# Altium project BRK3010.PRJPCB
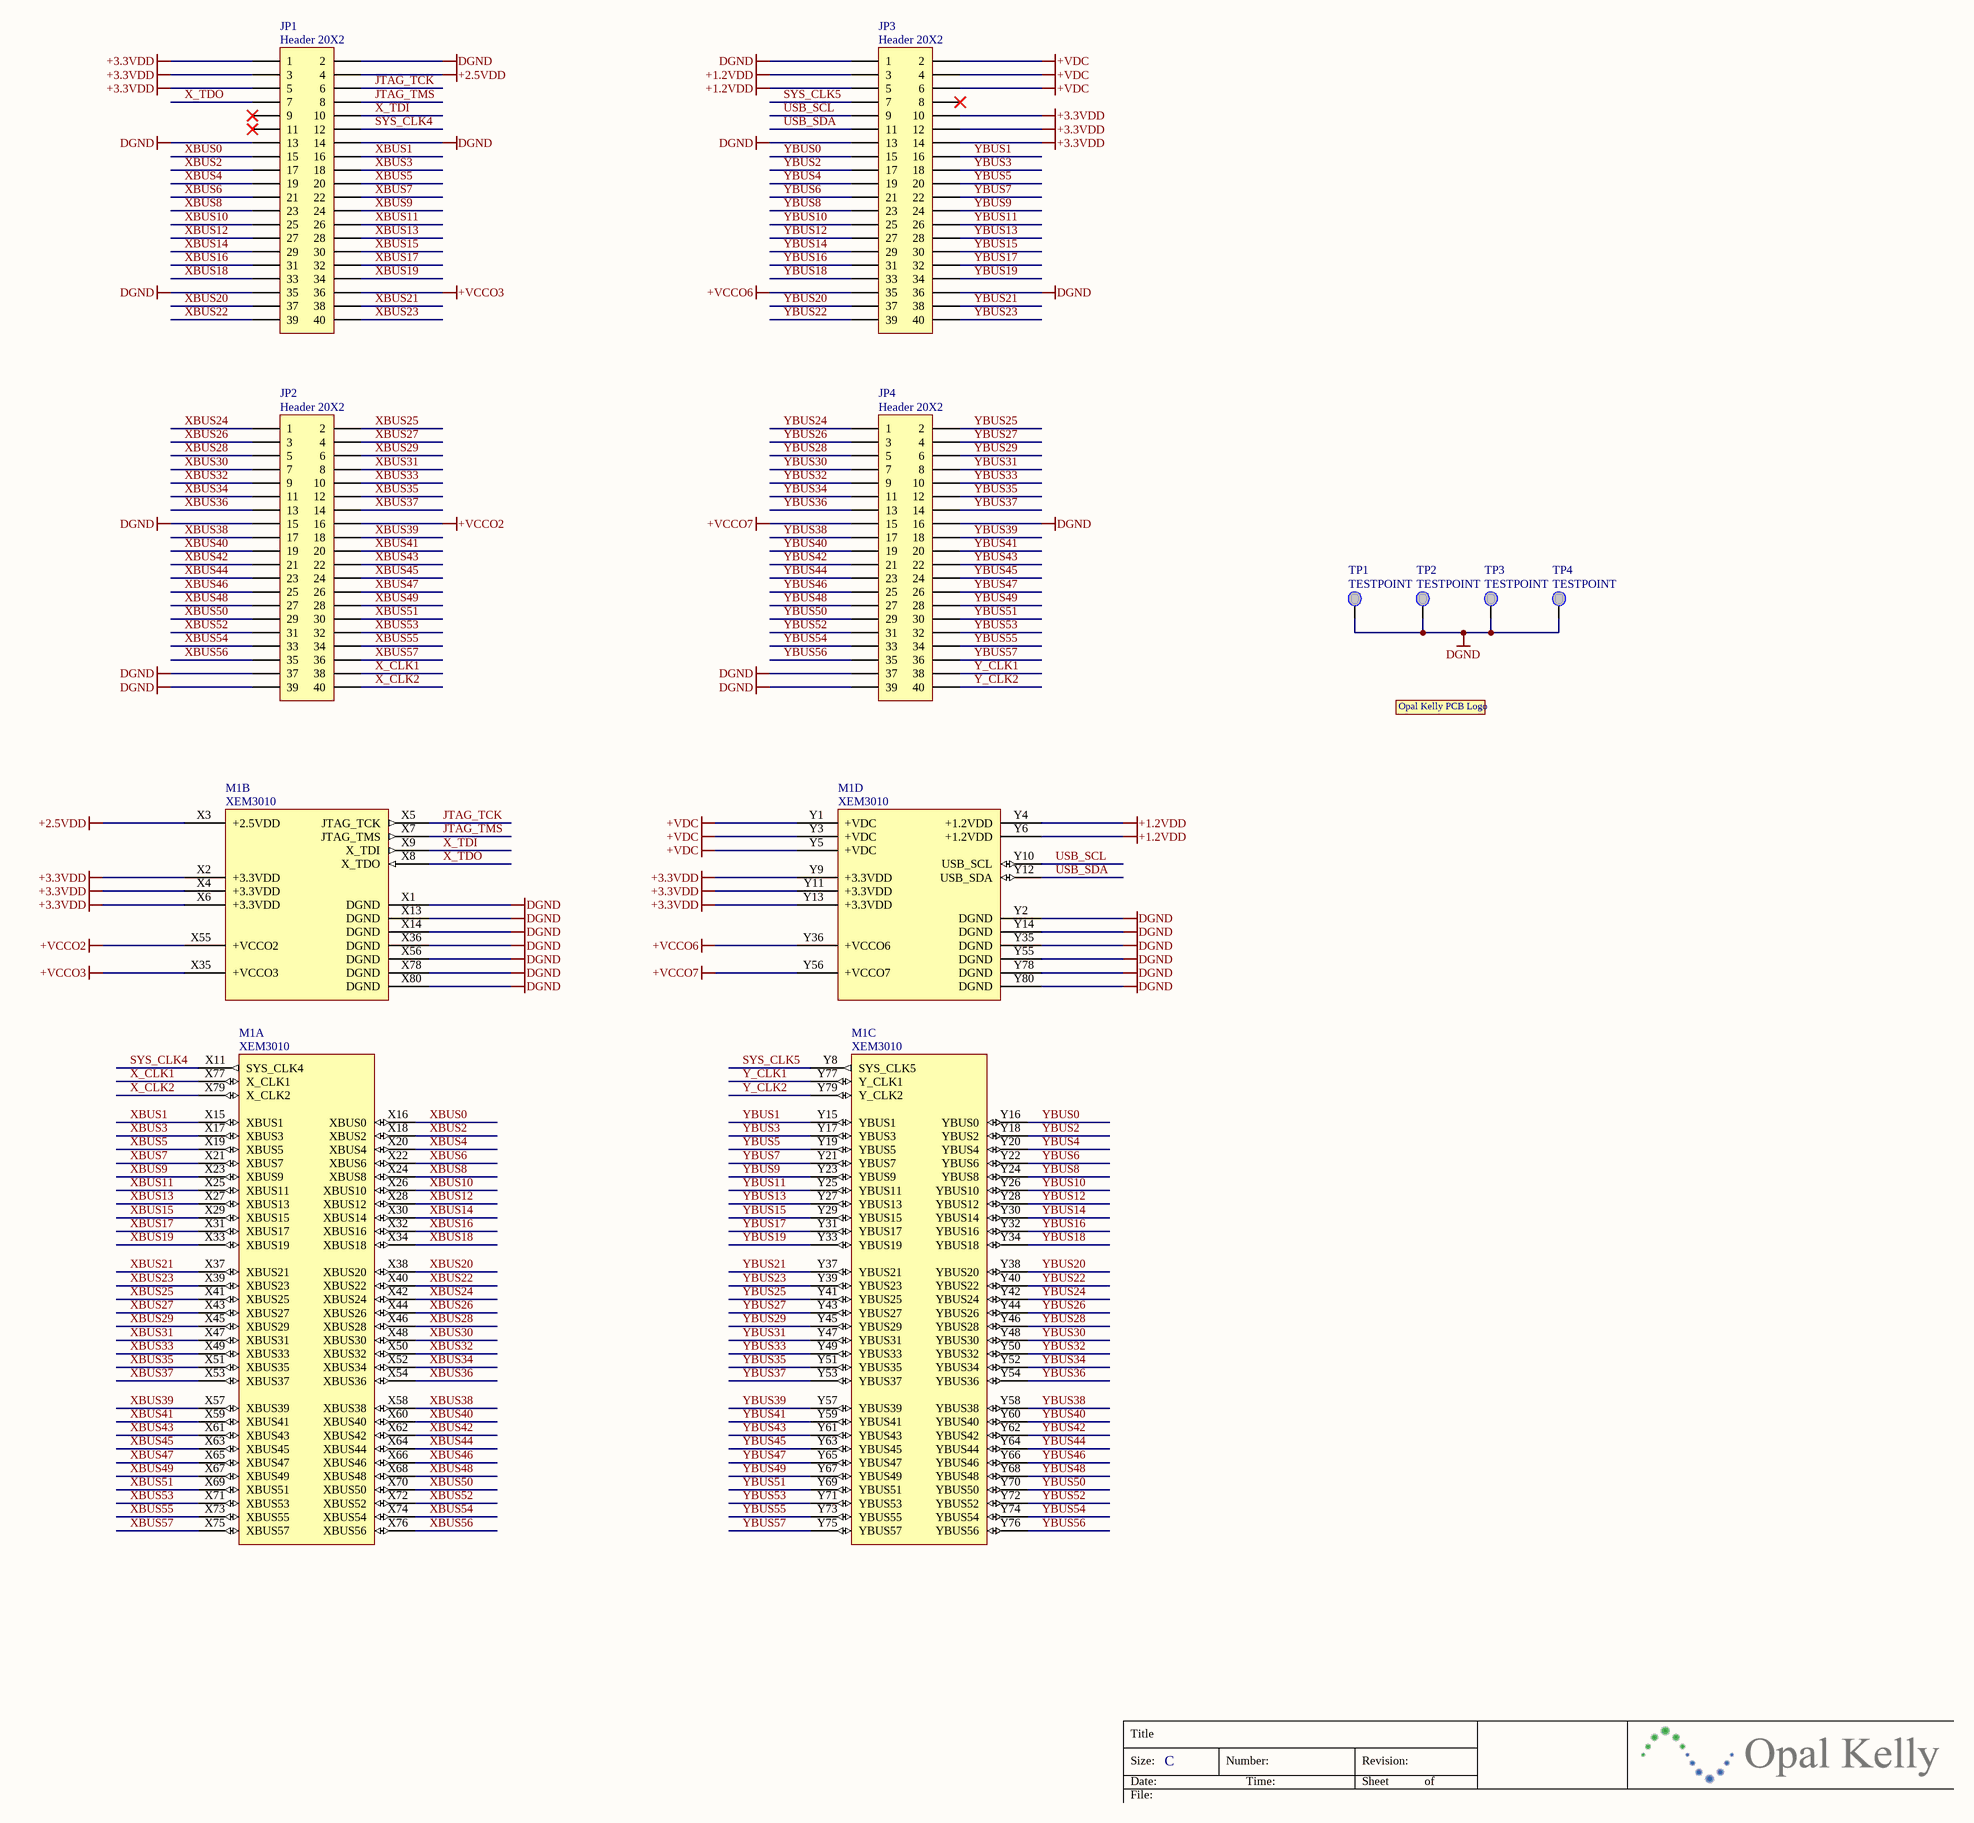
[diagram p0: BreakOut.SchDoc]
1 sheet, 10 parts. Net scope: global (net labels, ports and power ports of the same name join across sheets).
Board file: BreakOut.PcbDoc

## Sheet BreakOut.SchDoc: BRK3010
size C; Author: Garrick Kremesec; Organization: Opal Kelly; Address1: 13500 SW 72nd Ave, STE 120; Address2: Portland, OR 97223; Address3: http://www.opalkelly.com; DocumentNumber: 1; Revision: 1.0; SheetNumber: 1; SheetTotal: 1

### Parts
JP1  Header 20X2  [HDR2X20]
JP2  Header 20X2  [HDR2X20]
JP3  Header 20X2  [HDR2X20]
JP4  Header 20X2  [HDR2X20]
M1  XEM3010  [XEM3010MODULE]  (parts A,B,C,D of 4)
TP1  TESTPOINT  [TP_MED]
TP2  TESTPOINT  [TP_MED]
TP3  TESTPOINT  [TP_MED]
TP4  TESTPOINT  [TP_MED]
  OKLOGO  [oklogosmall]  (value not drawn)

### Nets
+1.2VDD: JP3.3 JP3.5 M1.Y4(+1.2VDD) M1.Y6(+1.2VDD)
+2.5VDD: JP1.4 M1.X3(+2.5VDD)
+3.3VDD: JP1.1 JP1.3 JP1.5 JP3.10 JP3.12 JP3.14 M1.X2(+3.3VDD) M1.X4(+3.3VDD) M1.X6(+3.3VDD) M1.Y9(+3.3VDD) M1.Y11(+3.3VDD) M1.Y13(+3.3VDD)
+VCCO2: JP2.16 M1.X55(+VCCO2)
+VCCO3: JP1.36 M1.X35(+VCCO3)
+VCCO6: JP3.35 M1.Y36(+VCCO6)
+VCCO7: JP4.15 M1.Y56(+VCCO7)
+VDC: JP3.2 JP3.4 JP3.6 M1.Y1(+VDC) M1.Y3(+VDC) M1.Y5(+VDC)
DGND: JP1.2 JP1.13 JP1.14 JP1.35 JP2.15 JP2.37 JP2.39 JP3.1 JP3.13 JP3.36 JP4.16 JP4.37 JP4.39 M1.X1(DGND) M1.X13(DGND) M1.X14(DGND) M1.X36(DGND) M1.X56(DGND) M1.X78(DGND) M1.X80(DGND) M1.Y2(DGND) M1.Y14(DGND) M1.Y35(DGND) M1.Y55(DGND) M1.Y78(DGND) M1.Y80(DGND) TP1.1(PIN) TP2.1(PIN) TP3.1(PIN) TP4.1(PIN)
JTAG_TCK: JP1.6 M1.X5(JTAG_TCK)
JTAG_TMS: JP1.8 M1.X7(JTAG_TMS)
SYS_CLK4: JP1.12 M1.X11(SYS_CLK4)
SYS_CLK5: JP3.7 M1.Y8(SYS_CLK5)
USB_SCL: JP3.9 M1.Y10(USB_SCL)
USB_SDA: JP3.11 M1.Y12(USB_SDA)
X_CLK1: JP2.38 M1.X77(X_CLK1)
X_CLK2: JP2.40 M1.X79(X_CLK2)
X_TDI: JP1.10 M1.X9(X_TDI)
X_TDO: JP1.7 M1.X8(X_TDO)
XBUS0: JP1.15 M1.X16(XBUS0)
XBUS1: JP1.16 M1.X15(XBUS1)
XBUS2: JP1.17 M1.X18(XBUS2)
XBUS3: JP1.18 M1.X17(XBUS3)
XBUS4: JP1.19 M1.X20(XBUS4)
XBUS5: JP1.20 M1.X19(XBUS5)
XBUS6: JP1.21 M1.X22(XBUS6)
XBUS7: JP1.22 M1.X21(XBUS7)
XBUS8: JP1.23 M1.X24(XBUS8)
XBUS9: JP1.24 M1.X23(XBUS9)
XBUS10: JP1.25 M1.X26(XBUS10)
XBUS11: JP1.26 M1.X25(XBUS11)
XBUS12: JP1.27 M1.X28(XBUS12)
XBUS13: JP1.28 M1.X27(XBUS13)
XBUS14: JP1.29 M1.X30(XBUS14)
XBUS15: JP1.30 M1.X29(XBUS15)
XBUS16: JP1.31 M1.X32(XBUS16)
XBUS17: JP1.32 M1.X31(XBUS17)
XBUS18: JP1.33 M1.X34(XBUS18)
XBUS19: JP1.34 M1.X33(XBUS19)
XBUS20: JP1.37 M1.X38(XBUS20)
XBUS21: JP1.38 M1.X37(XBUS21)
XBUS22: JP1.39 M1.X40(XBUS22)
XBUS23: JP1.40 M1.X39(XBUS23)
XBUS24: JP2.1 M1.X42(XBUS24)
XBUS25: JP2.2 M1.X41(XBUS25)
XBUS26: JP2.3 M1.X44(XBUS26)
XBUS27: JP2.4 M1.X43(XBUS27)
XBUS28: JP2.5 M1.X46(XBUS28)
XBUS29: JP2.6 M1.X45(XBUS29)
XBUS30: JP2.7 M1.X48(XBUS30)
XBUS31: JP2.8 M1.X47(XBUS31)
XBUS32: JP2.9 M1.X50(XBUS32)
XBUS33: JP2.10 M1.X49(XBUS33)
XBUS34: JP2.11 M1.X52(XBUS34)
XBUS35: JP2.12 M1.X51(XBUS35)
XBUS36: JP2.13 M1.X54(XBUS36)
XBUS37: JP2.14 M1.X53(XBUS37)
XBUS38: JP2.17 M1.X58(XBUS38)
XBUS39: JP2.18 M1.X57(XBUS39)
XBUS40: JP2.19 M1.X60(XBUS40)
XBUS41: JP2.20 M1.X59(XBUS41)
XBUS42: JP2.21 M1.X62(XBUS42)
XBUS43: JP2.22 M1.X61(XBUS43)
XBUS44: JP2.23 M1.X64(XBUS44)
XBUS45: JP2.24 M1.X63(XBUS45)
XBUS46: JP2.25 M1.X66(XBUS46)
XBUS47: JP2.26 M1.X65(XBUS47)
XBUS48: JP2.27 M1.X68(XBUS48)
XBUS49: JP2.28 M1.X67(XBUS49)
XBUS50: JP2.29 M1.X70(XBUS50)
XBUS51: JP2.30 M1.X69(XBUS51)
XBUS52: JP2.31 M1.X72(XBUS52)
XBUS53: JP2.32 M1.X71(XBUS53)
XBUS54: JP2.33 M1.X74(XBUS54)
XBUS55: JP2.34 M1.X73(XBUS55)
XBUS56: JP2.35 M1.X76(XBUS56)
XBUS57: JP2.36 M1.X75(XBUS57)
Y_CLK1: JP4.38 M1.Y77(Y_CLK1)
Y_CLK2: JP4.40 M1.Y79(Y_CLK2)
YBUS0: JP3.15 M1.Y16(YBUS0)
YBUS1: JP3.16 M1.Y15(YBUS1)
YBUS2: JP3.17 M1.Y18(YBUS2)
YBUS3: JP3.18 M1.Y17(YBUS3)
YBUS4: JP3.19 M1.Y20(YBUS4)
YBUS5: JP3.20 M1.Y19(YBUS5)
YBUS6: JP3.21 M1.Y22(YBUS6)
YBUS7: JP3.22 M1.Y21(YBUS7)
YBUS8: JP3.23 M1.Y24(YBUS8)
YBUS9: JP3.24 M1.Y23(YBUS9)
YBUS10: JP3.25 M1.Y26(YBUS10)
YBUS11: JP3.26 M1.Y25(YBUS11)
YBUS12: JP3.27 M1.Y28(YBUS12)
YBUS13: JP3.28 M1.Y27(YBUS13)
YBUS14: JP3.29 M1.Y30(YBUS14)
YBUS15: JP3.30 M1.Y29(YBUS15)
YBUS16: JP3.31 M1.Y32(YBUS16)
YBUS17: JP3.32 M1.Y31(YBUS17)
YBUS18: JP3.33 M1.Y34(YBUS18)
YBUS19: JP3.34 M1.Y33(YBUS19)
YBUS20: JP3.37 M1.Y38(YBUS20)
YBUS21: JP3.38 M1.Y37(YBUS21)
YBUS22: JP3.39 M1.Y40(YBUS22)
YBUS23: JP3.40 M1.Y39(YBUS23)
YBUS24: JP4.1 M1.Y42(YBUS24)
YBUS25: JP4.2 M1.Y41(YBUS25)
YBUS26: JP4.3 M1.Y44(YBUS26)
YBUS27: JP4.4 M1.Y43(YBUS27)
YBUS28: JP4.5 M1.Y46(YBUS28)
YBUS29: JP4.6 M1.Y45(YBUS29)
YBUS30: JP4.7 M1.Y48(YBUS30)
YBUS31: JP4.8 M1.Y47(YBUS31)
YBUS32: JP4.9 M1.Y50(YBUS32)
YBUS33: JP4.10 M1.Y49(YBUS33)
YBUS34: JP4.11 M1.Y52(YBUS34)
YBUS35: JP4.12 M1.Y51(YBUS35)
YBUS36: JP4.13 M1.Y54(YBUS36)
YBUS37: JP4.14 M1.Y53(YBUS37)
YBUS38: JP4.17 M1.Y58(YBUS38)
YBUS39: JP4.18 M1.Y57(YBUS39)
YBUS40: JP4.19 M1.Y60(YBUS40)
YBUS41: JP4.20 M1.Y59(YBUS41)
YBUS42: JP4.21 M1.Y62(YBUS42)
YBUS43: JP4.22 M1.Y61(YBUS43)
YBUS44: JP4.23 M1.Y64(YBUS44)
YBUS45: JP4.24 M1.Y63(YBUS45)
YBUS46: JP4.25 M1.Y66(YBUS46)
YBUS47: JP4.26 M1.Y65(YBUS47)
YBUS48: JP4.27 M1.Y68(YBUS48)
YBUS49: JP4.28 M1.Y67(YBUS49)
YBUS50: JP4.29 M1.Y70(YBUS50)
YBUS51: JP4.30 M1.Y69(YBUS51)
YBUS52: JP4.31 M1.Y72(YBUS52)
YBUS53: JP4.32 M1.Y71(YBUS53)
YBUS54: JP4.33 M1.Y74(YBUS54)
YBUS55: JP4.34 M1.Y73(YBUS55)
YBUS56: JP4.35 M1.Y76(YBUS56)
YBUS57: JP4.36 M1.Y75(YBUS57)

Not connected (* = marked no-connect by the designer): JP1 9* 11*; JP3 8*

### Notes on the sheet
- Title
- Size:
- Date:
- File:
- C
- Number:
- Time:
- Revision:
- Sheet
- of

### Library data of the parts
JP1-JP4 = Header 20X2: Header, 20-Pin, Dual row; Manufacturer: Generic Components; Class I: Connector
M1 = XEM3010: XEM3010 module connectors
 = OKLOGO: Opal Kelly PCB Logo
